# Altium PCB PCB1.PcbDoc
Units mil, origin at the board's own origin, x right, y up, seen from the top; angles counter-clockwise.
Board outline 2756 x 2756 mil, 4 copper layers (Top Layer, Internal Plane 1, Internal Plane 2, Bottom Layer), stack 18.2 mil thick; 11 components, 13 nets, 54 pads, 0 vias.
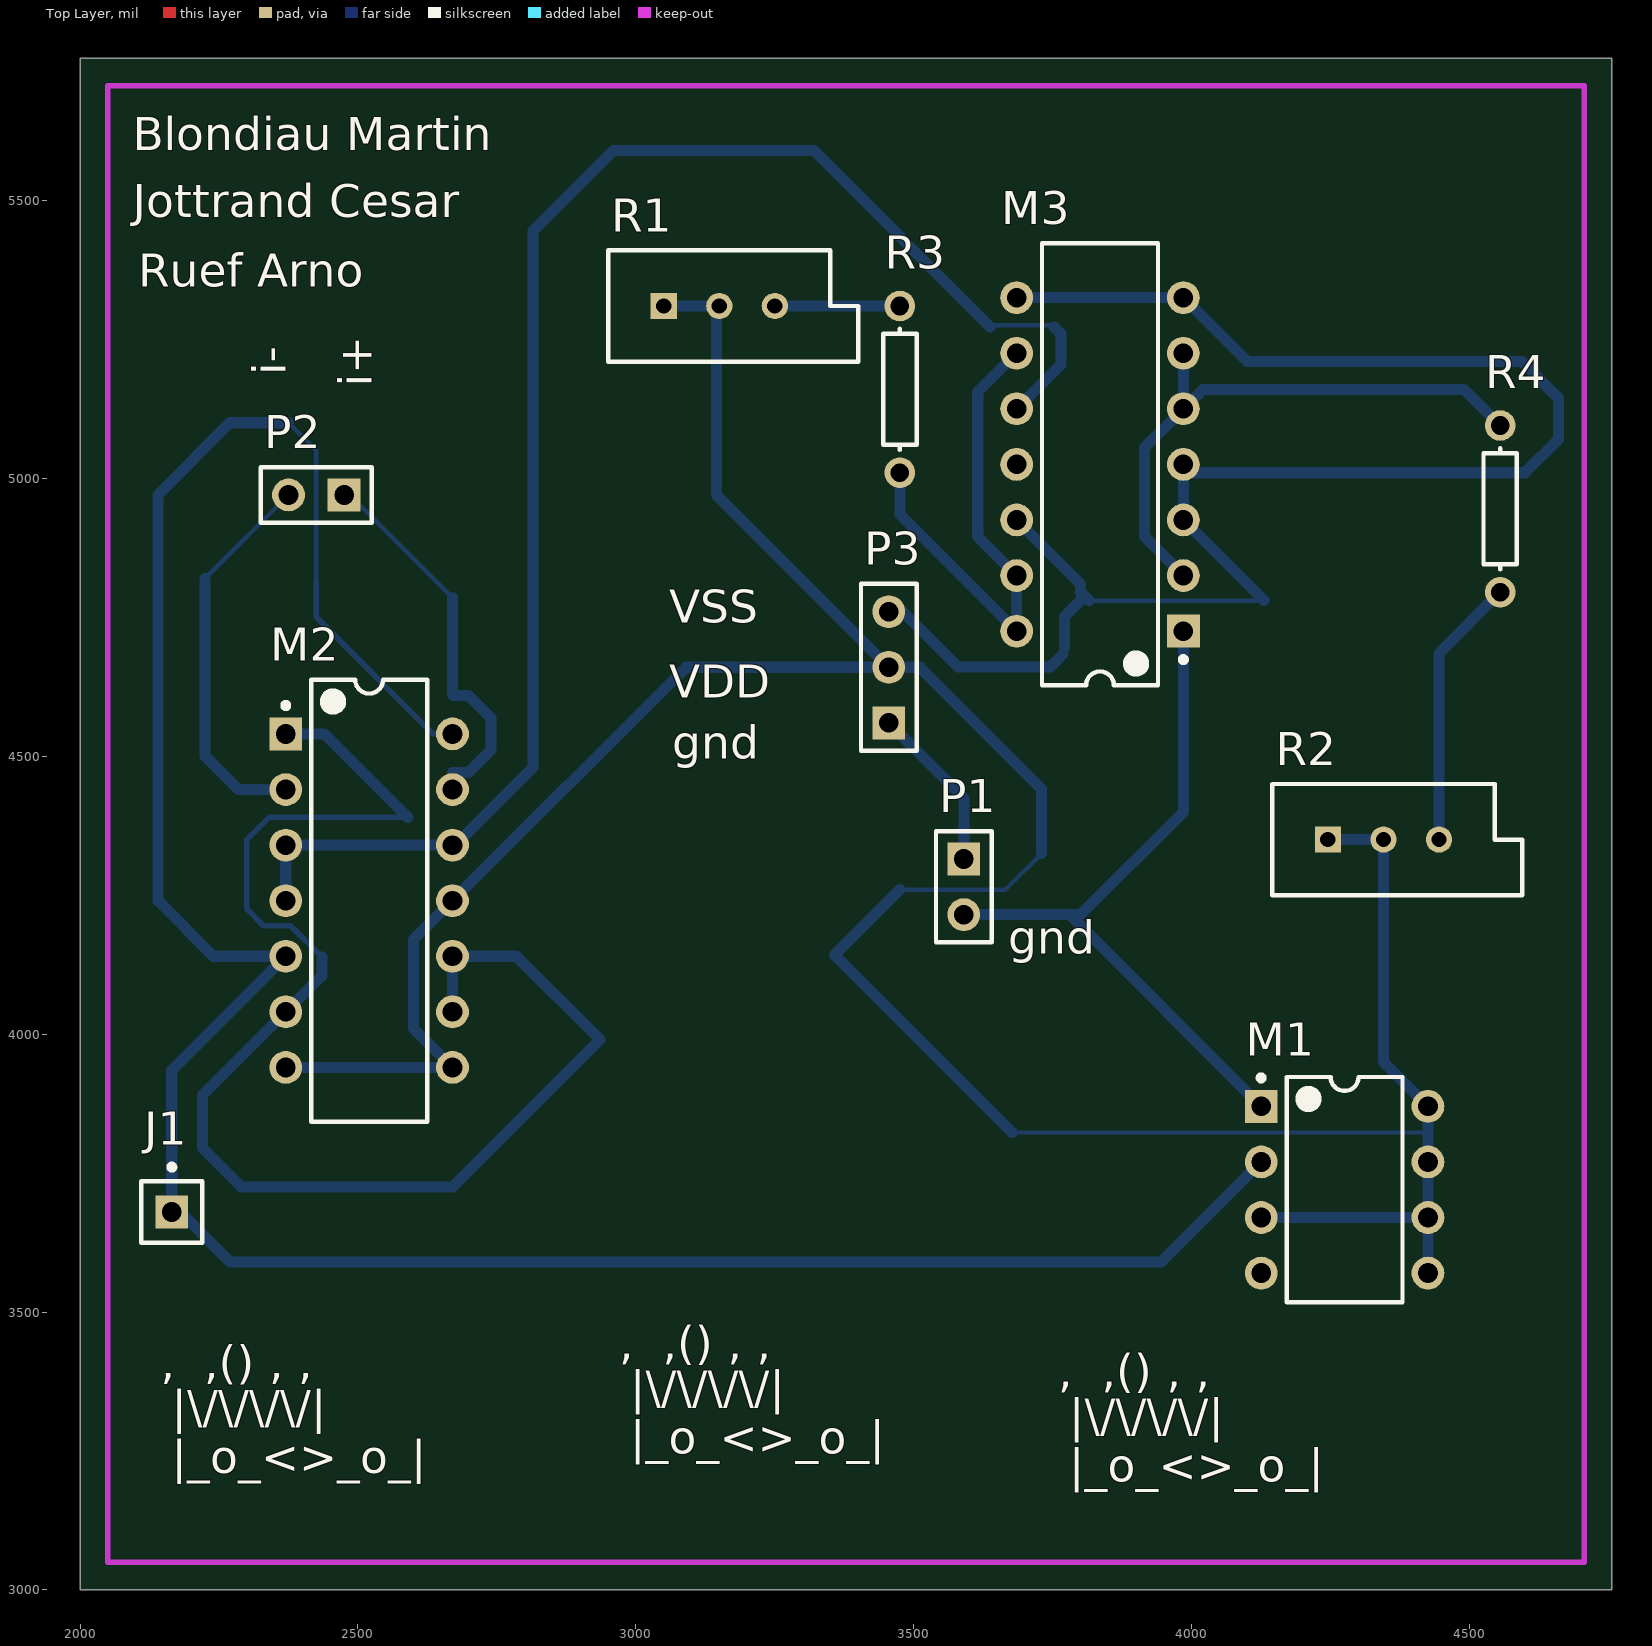
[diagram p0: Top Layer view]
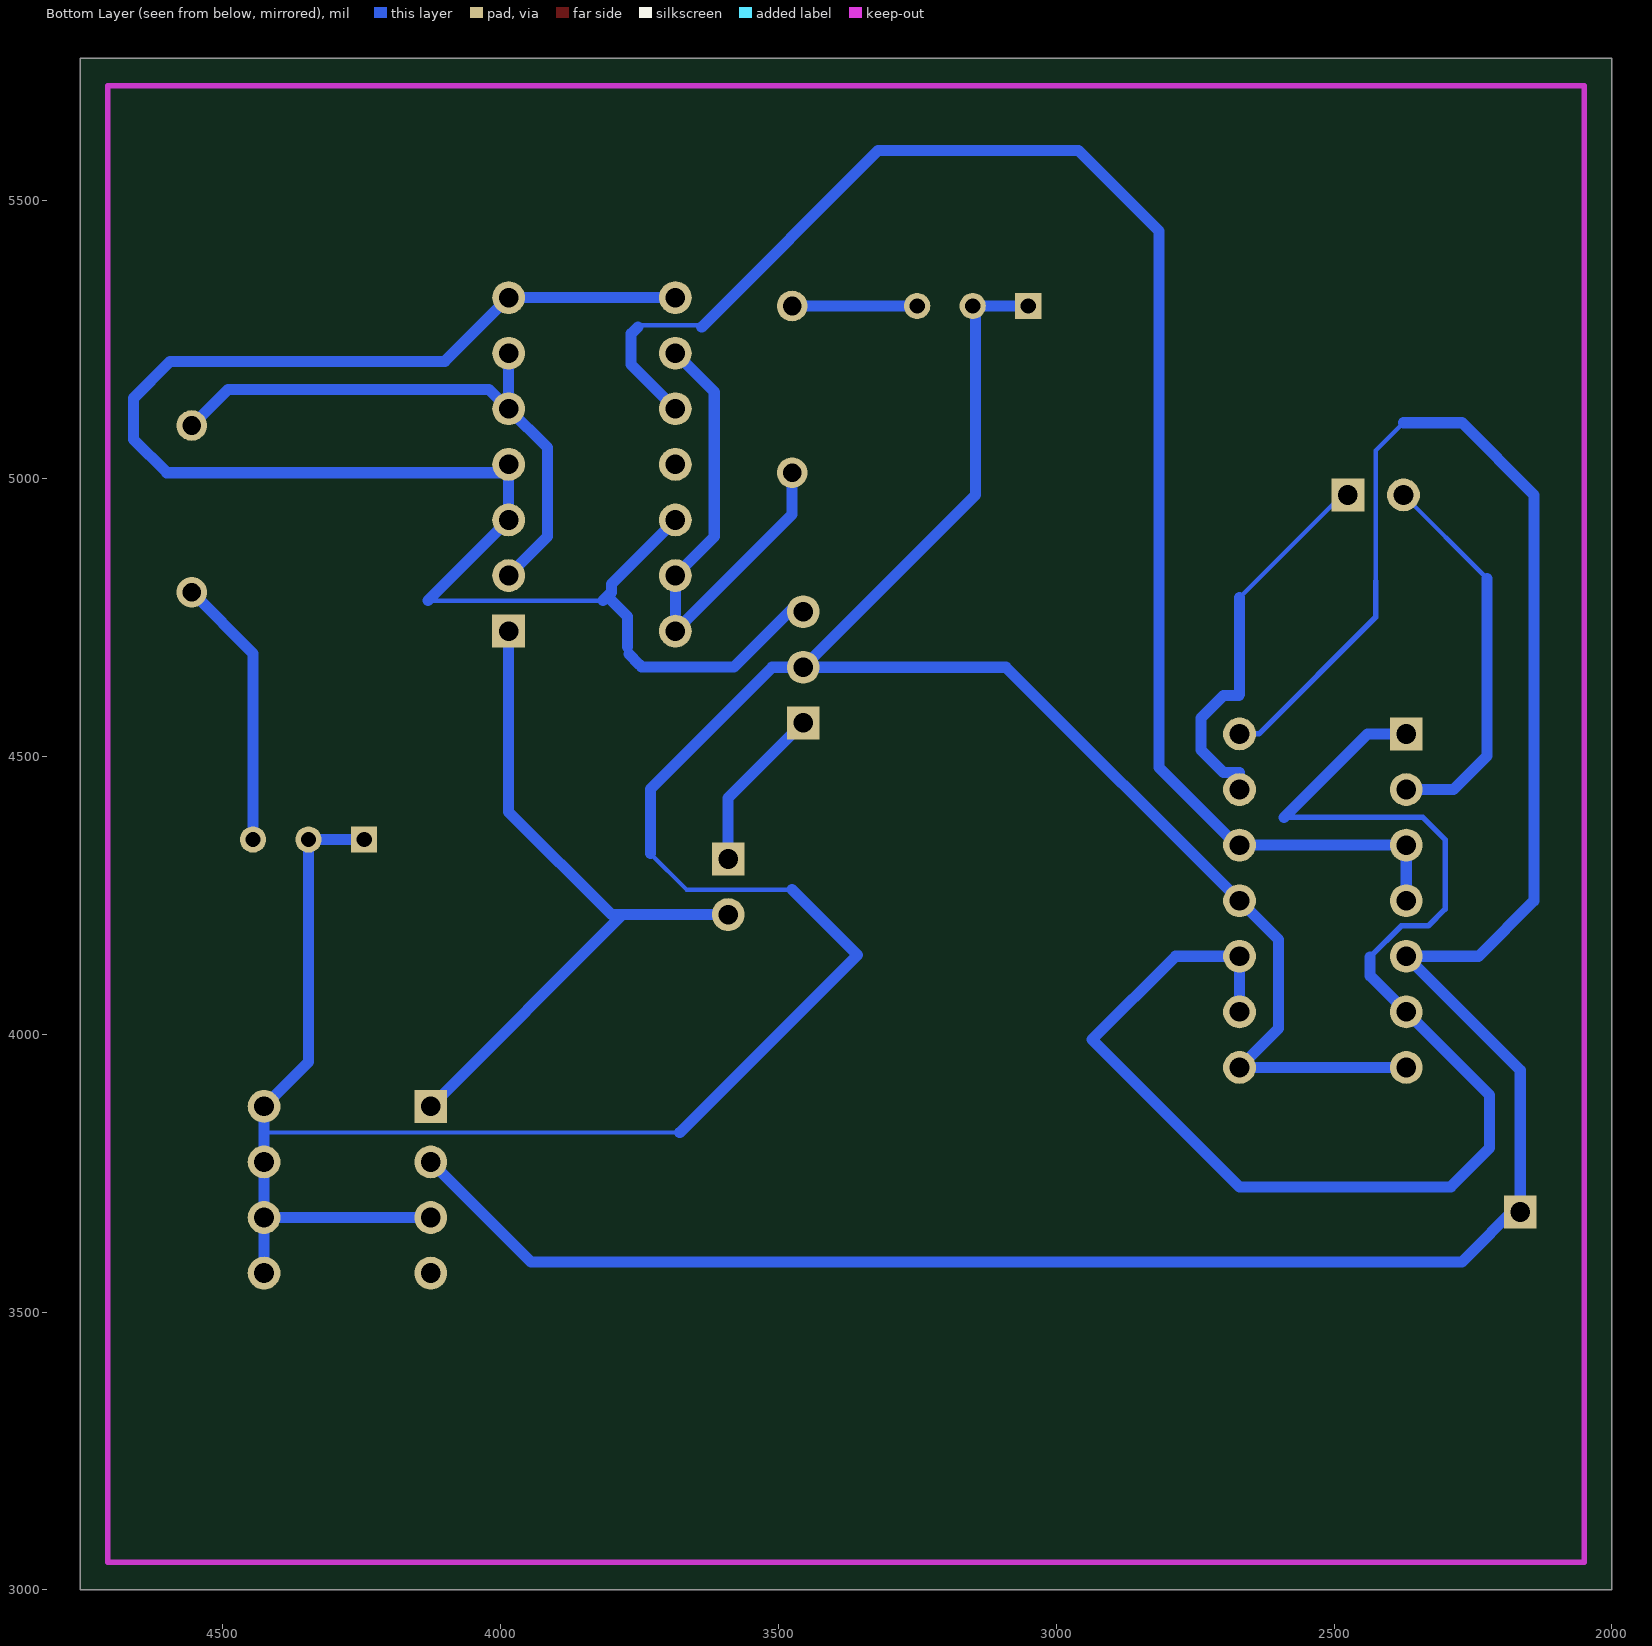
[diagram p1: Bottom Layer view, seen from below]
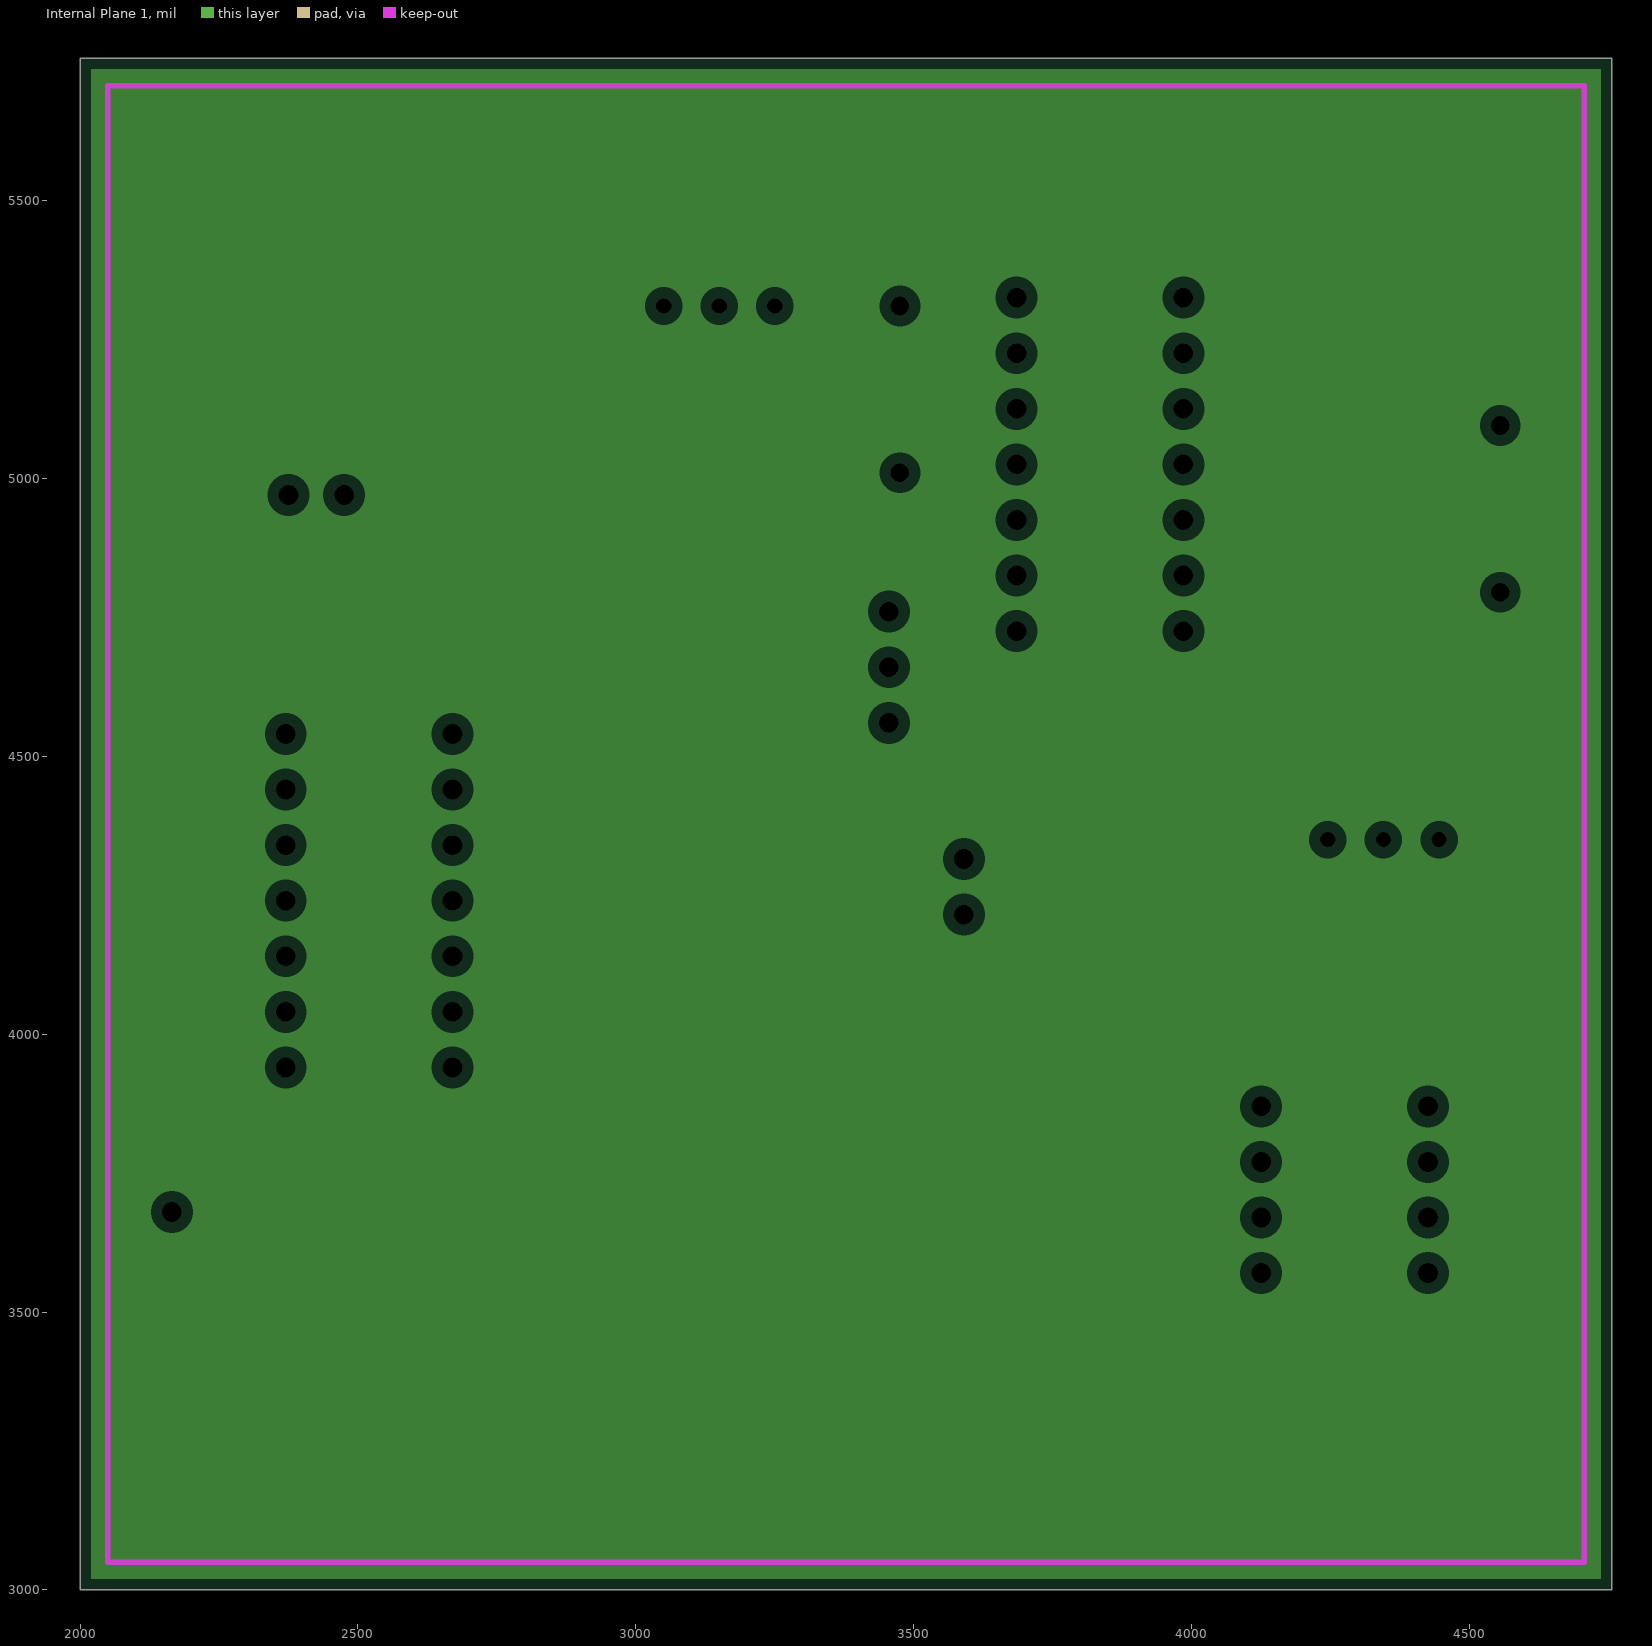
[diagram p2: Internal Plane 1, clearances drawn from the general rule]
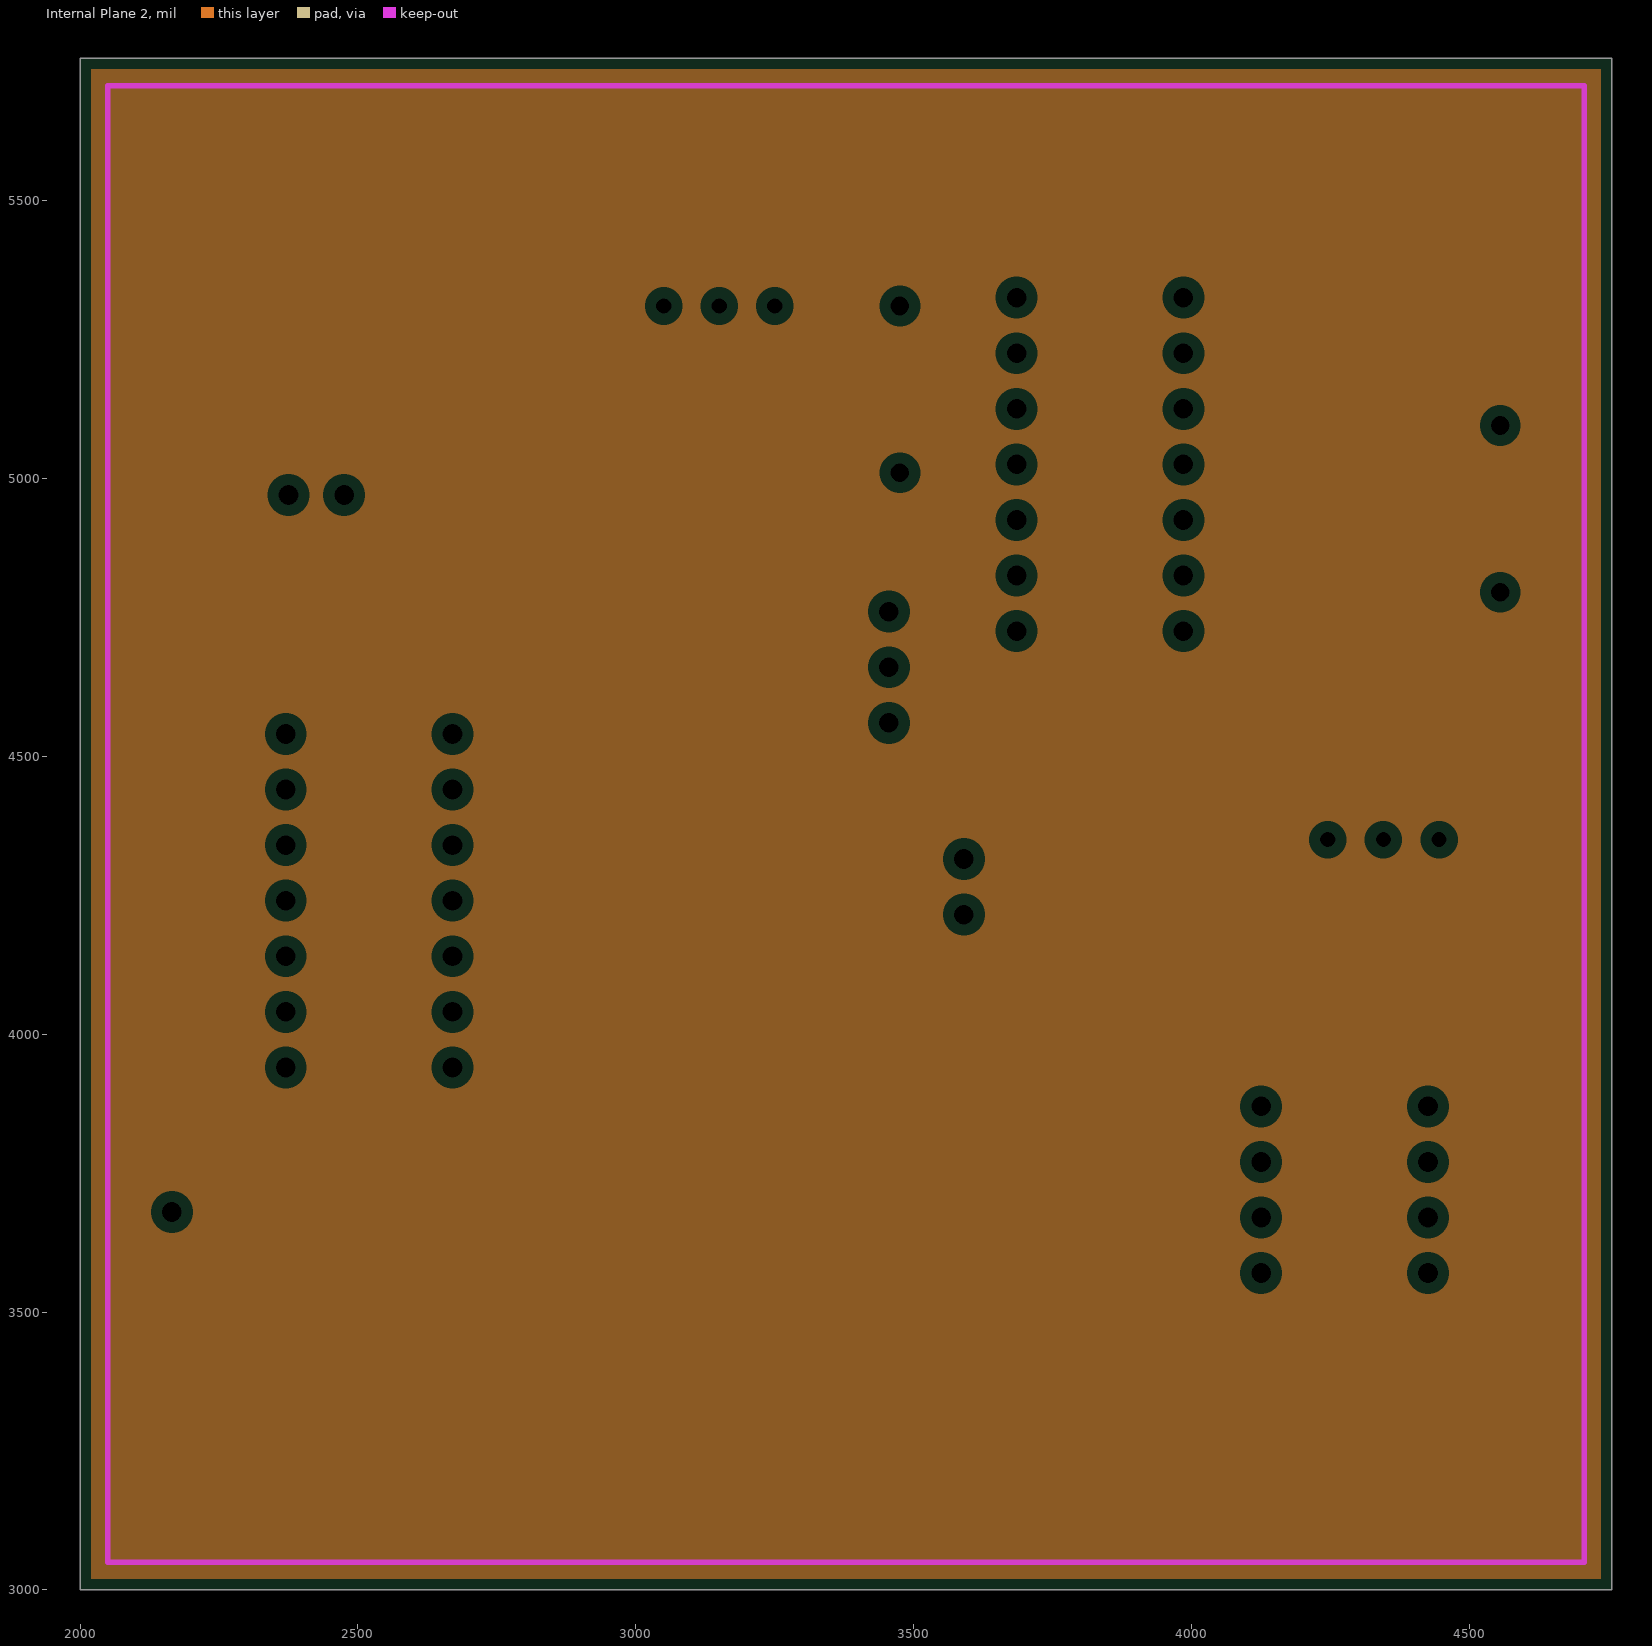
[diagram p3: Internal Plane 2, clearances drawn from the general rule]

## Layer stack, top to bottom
Top Solder: solder mask 0.4, Solder Resist, Dk 3.5
Top Layer: signal copper 1.4
Internal Plane 1: plane copper 1.4
Internal Plane 2: plane copper 1.4
Dielectric 1: dielectric 12.6, FR-4, Dk 4.8
Bottom Layer: signal copper 1.4
Bottom Solder: solder mask 0.4, Solder Resist, Dk 3.5

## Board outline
2000,3000 4756,3000 4756,5756 2000,5756

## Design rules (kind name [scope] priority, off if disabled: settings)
Clearance Clearance_1 [InNet('NetM2_1') or InNet('NetM2_3') or InNet('NetM3_3') or InNet('NETLABEL9') or InNet('NetJ1_1')] p1: gap=5
Clearance [All] p2: gap=30
PlaneClearance [All] p1: clearance=20
PlaneConnect [All] p1: planeconnectstyle=Relief reliefexpansion=20 reliefentries=4 reliefconductorwidth=10 reliefairgap=10
PolygonConnect [All] p1: connectstyle=Relief reliefconductorwidth=10 reliefentries=4 polygonreliefangle="90 Angle" airgapwidth=10
RoutingVias [All] p1: holewidth=32 width=62 viastyle="Through Hole" minholewidth=28 minwidth=50 maxholewidth=28 maxwidth=50
SolderMaskExpansion [All] p1: expansion=4
Width [All] p1: maxlimit=20 minlimit=8 preferedwidth=20 toplayer_minwidth=20 minimp=50.000000 maximp=50.000000 favimp=50.000000
28 further rules are at their usual default settings.

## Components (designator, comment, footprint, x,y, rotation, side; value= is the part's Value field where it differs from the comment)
J1 "Socket" PIN1 2165,3680 r0 top
M1 "ALD1117" DIP-8 4275,3720 r0 top
M2 "ALD1105" DIP-14 2520,4240 r0 top
M3 "ALD1106" DIP-14 3835,5025 r180 top
P1 "Header 2" HDR1X2 3590,4315 r270 top
P2 "Header 2" HDR1X2 2475,4970 r180 top
P3 "Header 3" HDR1X3 3455,4560 r90 top
R1 "RPot" VR5 3150,5310 r0 top
R2 "RPot" VR5 4345,4350 r0 top
R3 "Res1" AXIAL-0.3 3475,5160 r90 top
R4 "Res1" AXIAL-0.3 4555,4945 r270 top

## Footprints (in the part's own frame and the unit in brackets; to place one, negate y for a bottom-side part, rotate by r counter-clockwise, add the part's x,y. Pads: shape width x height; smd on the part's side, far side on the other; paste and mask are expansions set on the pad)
AXIAL-0.3 [mm] "Axial Device, Thru-Hole; 2 Leads; 0.3 in Pin Spacing"
  round 1.4 hole 0.85: 1(-3.81,0) 2(3.81,0)
  silkscreen extent -2.77,-0.76 2.77,0.76
DIP-8 [mm] "DIP, 8-Pin, Row Spacing 7.62 mm, Pitch 2.54 mm"
  rect 1.5x1.5 hole 0.9: 1(-3.81,3.81)
  round 1.5 hole 0.9: 2(-3.81,1.27) 3(-3.81,-1.27) 4(-3.81,-3.81) 5(3.81,-3.81) 6(3.81,-1.27) 7(3.81,1.27) 8(3.81,3.81)
  silkscreen extent -3.93,-5.15 2.65,5.23, body extent -3.6,-5.15 3.6,5.15, height 5.33
DIP-14 [mm] "DIP, 14-Pin, Row Spacing 7.62 mm, Pitch 2.54 mm"
  rect 1.5x1.5 hole 0.9: 1(-3.81,7.62)
  round 1.5 hole 0.9: 2(-3.81,5.08) 3(-3.81,2.54) 4(-3.81,0) 5(-3.81,-2.54) 6(-3.81,-5.08) 7(-3.81,-7.62) 8(3.81,-7.62) 9(3.81,-5.08) 10(3.81,-2.54) 11(3.81,0) 12(3.81,2.54) 13(3.81,5.08) 14(3.81,7.62)
  silkscreen extent -3.93,-10.1 2.65,10.1, body extent -3.6,-10.1 3.6,10.1, height 5.08
HDR1X2 [mm] "Connector; Header; 2 Position"
  rect 1.5x1.5 hole 0.9: 1(0,0)
  round 1.5 hole 0.9: 2(2.54,0)
  silkscreen extent -1.27,-1.27 3.81,1.27
HDR1X3 [mm] "Connector; Header; 3 Position"
  rect 1.5x1.5 hole 0.9: 1(0,0)
  round 1.5 hole 0.9: 2(2.54,0) 3(5.08,0)
  silkscreen extent -1.27,-1.27 6.35,1.27
PIN1 [mm] "Connector; Plug"
  rect 1.5x1.5 hole 0.9: 1(0,0)
  silkscreen extent -1.4,-1.4 1.4,2.17
VR5 [mm] "Thru-Hole; 3 Leads"
  rect 1.2x1.2 hole 0.7: 1(-2.54,0)
  round 1.2 hole 0.7: 2(0,0) 3(2.54,0)
  silkscreen extent -5.08,-2.54 6.35,2.54

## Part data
M1: "Dual P-channel matched MOSFET array"
M2: "Dual P-channel and dual N-channel matched MOSFET array"
M3: "Quad N-channel matched MOSFET array"
P1 P2: "Header, 2-Pin"
P3: "Header, 3-Pin"
R1 R2: "Potentiometer"
R3 R4: "Resistor"

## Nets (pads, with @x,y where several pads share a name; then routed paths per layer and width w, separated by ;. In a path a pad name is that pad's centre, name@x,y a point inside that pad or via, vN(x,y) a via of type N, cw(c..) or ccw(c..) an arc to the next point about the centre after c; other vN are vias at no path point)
GND: P1.1 P3.1 | length 300.9
  Bottom Layer w20: P3.1 3590,4425 P1.1
NetJ1_1: J1.1 M1.2 M2.5 M2.14 | length 4600.9
  Bottom Layer w8: 2375,5100 2425,5050 2425,4815
  Bottom Layer w10: 2425,4815 2425,4750 2635,4540 M2.14
  Bottom Layer w20: 2375,5100 2270,5100 2140,4970 2140,4240 2240,4140 M2.5 2165,3935 2165,3695 2270,3590 3945,3590 M1.2
NETLABEL5: M2.13 P2.1 | length 679.6
  Bottom Layer w8: P2.1@2497.5,4957.5 2670,4785
  Bottom Layer w20: M2.13 2670,4470.47 2698.8,4470.47 2739.53,4511.2 2739.53,4568.8 2698.8,4609.53 2671.18,4609.53 2670,4610.71 2670,4785
NETLABEL7: M2.2 P2.2 | length 702
  Bottom Layer w8: 2225,4820 P2.2
  Bottom Layer w20: 2225,4820 2225,4500 2285,4440 M2.2
NETLABEL9: M1.3 M1.5 M1.6 M1.7 M1.8 M2.7 M2.8 M2.11 P3.2 R1.1 R1.2 R2.1 R2.2 | length 5837.3
  Bottom Layer w8: 3475,4260 3665,4260 3730,4325 ; 3677.03,3822.97 4420,3822.97
  Bottom Layer w20: M2.7 M2.8 2600,4010 2600,4170 M2.11 3090,4660 P3.2 ; R1.1@3045,5300 3055,5310 3145,5310 3145,4970 P3.2 ; 3475,4260 3357.5,4142.5 3677.03,3822.97 ; 3730,4325 3730,4441 3511,4660 P3.2 ; M1.3 M1.6 ; R2.1 R2.2 4345,3950 M1.8 M1.7 M1.6 ; M1.5 M1.6
NetM1_1: M1.1 M3.1 P1.2 | length 1474.5
  Bottom Layer w20: M3.1 3985,4400 3800,4215 P1.2 3780,4215 M1.1
NetM2_1: M2.1 M2.6 M2.9 M2.10 | length 2598.1
  Bottom Layer w10: 2435,4138.75 2378.75,4195 2330,4195 2300,4225 2300,4350 2340,4390 2590,4390
  Bottom Layer w20: M2.1 2440,4540 2590,4390 ; 2435,4138.75 2435,4105 M2.6 2220,3890 2220,3795 2290,3725 2670,3725 2935,3990 2785,4140 M2.10 M2.9
NetM2_3: M2.3 M2.4 M2.12 M3.10 | length 2891.8
  Bottom Layer w8: 3637.5,5272.5 3640,5275 3752.5,5275
  Bottom Layer w10: M3.10@3690,5115 3700,5125 M3.10@3700,5140
  Bottom Layer w20: M2.4 M2.3 2675,4340 2815,4480 2815,5445 2960,5590 3320,5590 3637.5,5272.5 ; M3.10@3700,5140 3765,5205 3765,5260 3752.5,5272.5
NetM3_2: M3.2 M3.5 M3.6 R4.1 | length 1069.4
  Bottom Layer w20: M3.2 3915,4895 3915,5055 M3.5 ; M3.6 M3.5 ; R4.1 4490,5160 4020,5160 M3.5
NetM3_3: M3.3 M3.4 M3.7 M3.8 M3.12 P3.3 | length 3134
  Bottom Layer w8: 3768.75,4683.75 3768.75,4693.75 3771.25,4696.25 ; 3800,4780 3815,4780 4130,4780
  Bottom Layer w10: 3745.47,4660.47 3750,4665
  Bottom Layer w20: P3.3@3465,4775 3579.53,4660.47 3745.47,4660.47 ; M3.12 3800,4810 3800,4795 3815,4780 ; M3.8 M3.7 4100,5210 4594,5210 4660,5144 4660,5070 4600,5010 4000,5010 M3.4 M3.3 4130,4780 ; 3750,4665 3768.75,4683.75 ; 3771.25,4696.25 3771.25,4751.25 3800,4780
NetM3_9: M3.9 M3.13 M3.14 R3.1 | length 930
  Bottom Layer w20: R3.1 3475,4935 M3.14 M3.13 3615,4895 3615,5155 M3.9
NetR1_3: R1.3 R3.2 | length 225
  Bottom Layer w20: R1.3 R3.2
NetR2_3: R2.3 R4.2 | length 490.6
  Bottom Layer w20: R2.3 4445,4685 R4.2
pads on no net: M1.4 M3.11

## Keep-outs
Keep-Out Layer:
  lines w10: 2050,3050 2050,5706 4706,5706 4706,3050 2050,3050

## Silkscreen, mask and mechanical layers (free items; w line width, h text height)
Top Overlay:
  text "Blondiau Martin" at 2095,5590 h60
  text "Jottrand Cesar" at 2095,5470 h60
  text "Ruef Arno" at 2105,5345 h60
  text "i-" at 2370,5185 h60 r90
  text "i+" at 2525,5165 h60 r90
  text "VSS" at 3060,4740 h60
  text "VDD" at 3060,4605.01 h60
  text "gnd" at 3065,4495.01 h60
  text "gnd" at 3670,4145.01 h60
  text ",  ,() , ," at 2970,3415 h60
  text ",  ,() , ," at 2145,3380 h60
  text ",  ,() , ," at 3760,3365 h60
  text "|\/\/\/\/|" at 2990,3335 h60
  text "|\/\/\/\/|" at 2165,3300 h60
  text "|\/\/\/\/|" at 3780,3285 h60
  text "|_o_<>_o_|" at 2990,3245 h60
  text "|_o_<>_o_|" at 2165,3210 h60
  text "|_o_<>_o_|" at 3780,3195 h60

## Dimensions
2050,3050 to 2050,5706 on Mechanical 1
2050,3050 to 4706,3050 on Mechanical 1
